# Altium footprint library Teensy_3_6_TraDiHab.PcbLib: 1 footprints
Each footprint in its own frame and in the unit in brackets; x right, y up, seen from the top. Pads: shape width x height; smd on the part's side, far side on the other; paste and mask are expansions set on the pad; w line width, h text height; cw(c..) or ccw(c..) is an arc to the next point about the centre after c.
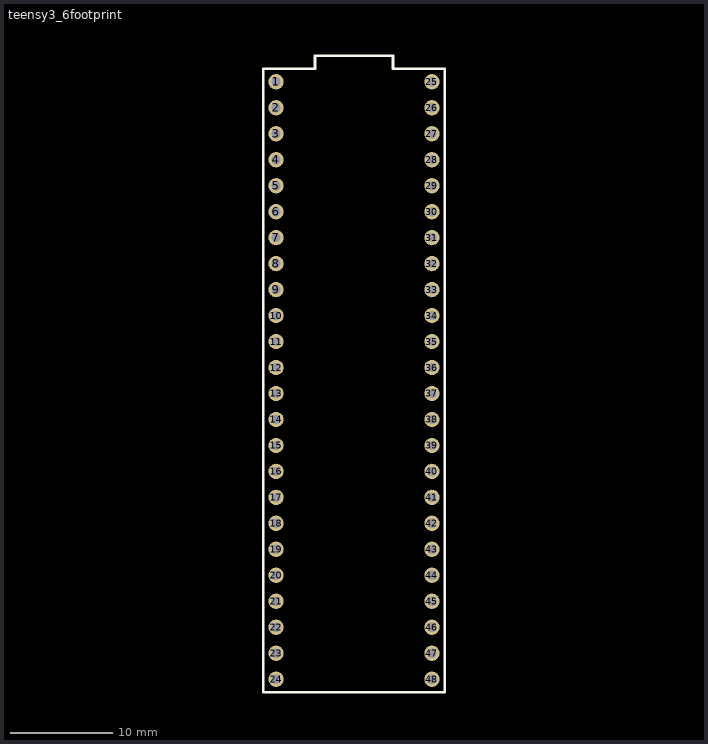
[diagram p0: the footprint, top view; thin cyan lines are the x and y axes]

## teensy3_6footprint [mm]
pads (48):
  round 1.5 hole 0.9: 1(-165.1,160.02) 2(-165.1,157.48) 3(-165.1,154.94) 4(-165.1,152.4) 5(-165.1,149.86) 6(-165.1,147.32) 7(-165.1,144.78) 8(-165.1,142.24) 9(-165.1,139.7) 10(-165.1,137.16) 11(-165.1,134.62) 12(-165.1,132.08) 13(-165.1,129.54) 14(-165.1,127) 15(-165.1,124.46) 16(-165.1,121.92) 17(-165.1,119.38) 18(-165.1,116.84) 19(-165.1,114.3) 20(-165.1,111.76) 21(-165.1,109.22) 22(-165.1,106.68) 23(-165.1,104.14) 24(-165.1,101.6) 25(-149.86,160.02) 26(-149.86,157.48) 27(-149.86,154.94) 28(-149.86,152.4) 29(-149.86,149.86) 30(-149.86,147.32) 31(-149.86,144.78) 32(-149.86,142.24) 33(-149.86,139.7) 34(-149.86,137.16) 35(-149.86,134.62) 36(-149.86,132.08) 37(-149.86,129.54) 38(-149.86,127) 39(-149.86,124.46) 40(-149.86,121.92) 41(-149.86,119.38) 42(-149.86,116.84) 43(-149.86,114.3) 44(-149.86,111.76) 45(-149.86,109.22) 46(-149.86,106.68) 47(-149.86,104.14) 48(-149.86,101.6)
Top Overlay:
  lines w0.254: -166.37,100.33 -166.37,161.29 -161.29,161.29 -161.29,162.56 -153.67,162.56 -153.67,161.29 -148.59,161.29 -148.59,100.33 -166.37,100.33
3D body: height 14, standoff 10, extent -166.497,100.203 -148.463,162.687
